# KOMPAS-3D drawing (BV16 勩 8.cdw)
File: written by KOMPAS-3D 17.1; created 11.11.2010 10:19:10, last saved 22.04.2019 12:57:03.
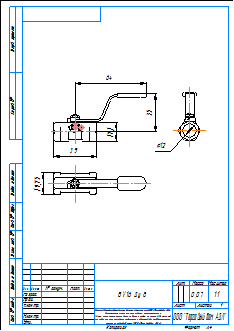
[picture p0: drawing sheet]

Sheet 1: A4, portrait

Title block, sheet 1: name: BV16 Ду 8; material: Внимание! Данный продукт является объектом авторского права ООО «Торговый Дом АДЛ». / Запрещается изменение, копирование, распространение / (в том числе путем копирования на другие сайты и ресурсы в Интернете) / или любое иное использование информации и объектов без предварительного / согласия правообладателя (ООО «Торговый Дом АДЛ»).; mass: 0,07; scale: 1:1; sheets: 1; organisation: ООО "Торговый дом АДЛ"; sheet format: A4; stored path: \\adlc.lan\data\АДЛ_ПКД\3D-модели\ADL production\Краны шаровые серии BV\BV16\KOMPAS 2D\BV16 Ду 8.cdw

Views: Вид 1, Спереди 2, Проекционный вид 3, Проекционный вид 4
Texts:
  user
  adl
Dimensions and other numbers on the sheet: 19,75; 12; 39; 17,1; 35; 64; 1:1; 1; 0,07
